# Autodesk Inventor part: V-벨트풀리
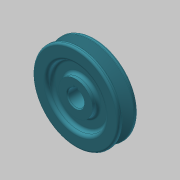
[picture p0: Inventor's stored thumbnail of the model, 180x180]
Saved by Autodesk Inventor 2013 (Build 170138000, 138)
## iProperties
Created: 2019-01
Part Number: V-벨트풀리
Material: 알루미늄 6061
Document SubType Name: Modeling
Designer: mduedu
Density: 1 g/cm^3
Author: mduedu
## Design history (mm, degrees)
sketch "스케치1"
  geometry: L1 (-10, 0)-(10, 0); L2 (10, 0)-(10, 44.5); L3 (10, 44.5)-(-10, 44.5); L4 (-10, 44.5)-(-10, 0); L5 (0, 0)-(0, 44.5); L6 (-5.976, 44.5)-(-2.154, 32); L7 (-2.154, 32)-(2.154, 32); L8 (2.154, 32)-(5.976, 44.5); L9 (-10, 40)-(10, 40); 3 further points
  constraints: 18 end point, 8 point on line, 3 perpendicular, 2 midpoint, 2 parallel, 1 coincident, 1 horizontal, 1 other
  dimensions: "d0" = 89 diameter of L3 L1; "d2" = 20 distance of L2.end L3.end; "d3" = 34 deg angle of L8 L6; "d4" = 9.2 distance of point (4.6, 40) point (-4.6, 40); "d5" = 80 diameter of L9 L1; "d6" = 8 distance between parallel lines of L7 L9; "d7" = 4.5 distance between parallel lines of L3 L9 (derived)
revolve "회전1" sketch "스케치1" stored, may be unused: angle "d8" = 90 deg
fillet "모깎기1" dims "d9" = 0.5, "d10" = 1, "d11" = 2
sketch "스케치2"
  geometry: C1 r 17.5 at (0, 0); 1 further point
  constraints: 1 centre point, 1 coincident
  dimensions: "d12" = 35 diameter of C1
extrude "돌출1" join sketch "스케치2" distance "d13" = 10; taper "d14" = 0 deg
sketch "스케치3"
  geometry: L1 (-2.5, 8.124)-(2.5, 8.124); L2 (2.5, 8.124)-(2.5, 10.8); L3 (2.5, 10.8)-(-2.5, 10.8); L4 (-2.5, 10.8)-(-2.5, 8.124); A1 r 8.5 centre (0, 0) between (-2.5, 8.124) and (2.5, 8.124); 1 further point
  constraints: 8 end point, 2 parallel, 2 point on circle, 1 centre point, 1 coincident, 1 horizontal, 1 perpendicular
  dimensions: "d15" = 17 diameter of A1; "d16" = 5 distance of L2.end L3.end; "d17" = 19.3 dimension on A1 L3
extrude "돌출2" cut sketch "스케치3" stored distance "d18" = 10; taper "d19" = 0 deg
node "작업 평면1"
sketch "스케치4"
  geometry: L1 (-10, 17.5)-(-10, -17.5) reference; 2 further points
  constraints: 1 horizontal alignment
  dimensions: "d21" = 8 distance from line of point (-2, 0) L1
hole "구멍1" sketch "스케치4" at (-2, 0) diameter "d22" = 2.459; stored, may be unused: countersink angle "d26" = 90 deg, drill point angle "d28" = 118 deg; dims "d23" = 6, "d24" = 4, "d25" = 2, "d27" = 8
chamfer "모따기1" distance "d29" = 1; stored, may be unused: second distance "d30" = 2, angle "d31" = 45 deg
sketch "스케치5"
  geometry: C1 r 17.5 at (0, 0) reference; C2 r 30 at (0, 0); 1 further point
  constraints: 1 centre point, 1 coincident
  dimensions: "d37" = 60 diameter of C2
extrude "돌출3" cut sketch "스케치5" distance "d34" = 6; taper "d35" = 0 deg
fillet "모깎기4" dims "d38" = 3
node "솔리드1"
mirror "대칭1"
